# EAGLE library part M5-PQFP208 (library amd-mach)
AMD MACH SERIES
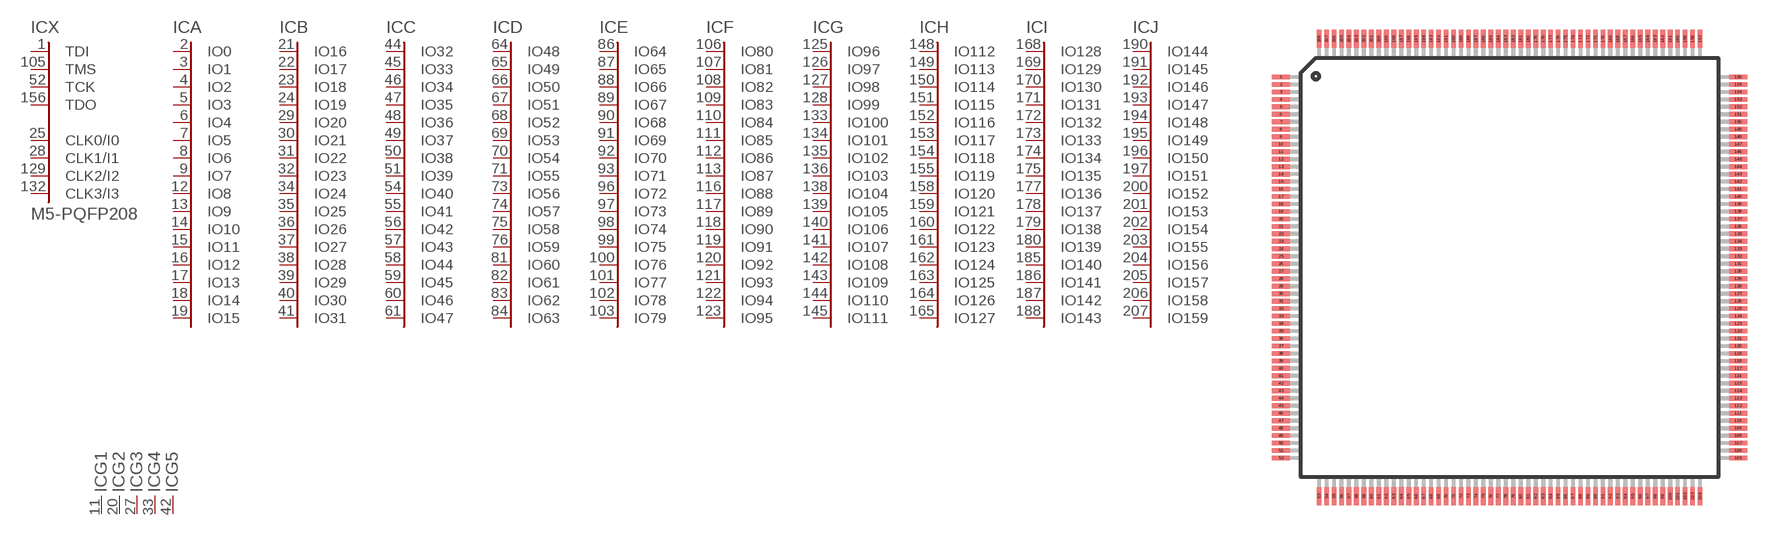
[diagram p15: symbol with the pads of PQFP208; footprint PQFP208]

Designator prefix IC; gates X=M5-CTRL A=IO15 B=IO31 C=IO47 D=IO63 E=IO79 F=IO95 G=IO111 H=IO127 I=IO143 J=IO159 G1=GND G2=GND G3=GND G4=GND G5=GND G6=GND G7=GND G8=GND G9=GND G10=GND G11=GND G12=GND G13=GND G14=GND G15=GND G16=GND G17=GND G18=GND G19=GND G20=GND G21=GND G22=GND G23=GND G24=GND G25=GND G26=GND V1=VCC V2=VCC V3=VCC V4=VCC V5=VCC V6=VCC V7=VCC V8=VCC V9=VCC V10=VCC V11=VCC V12=VCC V13=VCC V14=VCC

## M5-PQFP208 (OC_FARNELL: unknown; OC_NEWARK: unknown)  [PQFP208]
1  X:TDI  in
2  A:IO0
3  A:IO1
4  A:IO2
5  A:IO3
6  A:IO4
7  A:IO5
8  A:IO6
9  A:IO7
10  V1:VCC  pwr
11  G1:GND  pwr
12  A:IO8
13  A:IO9
14  A:IO10
15  A:IO11
16  A:IO12
17  A:IO13
18  A:IO14
19  A:IO15
20  G2:GND  pwr
21  B:IO16
22  B:IO17
23  B:IO18
24  B:IO19
25  X:CLK0/I0  in
26  V2:VCC  pwr
27  G3:GND  pwr
28  X:CLK1/I1  in
29  B:IO20
30  B:IO21
31  B:IO22
32  B:IO23
33  G4:GND  pwr
34  B:IO24
35  B:IO25
36  B:IO26
37  B:IO27
38  B:IO28
39  B:IO29
40  B:IO30
41  B:IO31
42  G5:GND  pwr
43  V3:VCC  pwr
44  C:IO32
45  C:IO33
46  C:IO34
47  C:IO35
48  C:IO36
49  C:IO37
50  C:IO38
51  C:IO39
52  X:TCK  in
53  G6:GND  pwr
54  C:IO40
55  C:IO41
56  C:IO42
57  C:IO43
58  C:IO44
59  C:IO45
60  C:IO46
61  C:IO47
62  G7:GND  pwr
63  V4:VCC  pwr
64  D:IO48
65  D:IO49
66  D:IO50
67  D:IO51
68  D:IO52
69  D:IO53
70  D:IO54
71  D:IO55
72  G8:GND  pwr
73  D:IO56
74  D:IO57
75  D:IO58
76  D:IO59
77  V5:VCC  pwr
78  G9:GND  pwr
79  G10:GND  pwr
80  V6:VCC  pwr
81  D:IO60
82  D:IO61
83  D:IO62
84  D:IO63
85  G11:GND  pwr
86  E:IO64
87  E:IO65
88  E:IO66
89  E:IO67
90  E:IO68
91  E:IO69
92  E:IO70
93  E:IO71
94  V7:VCC  pwr
95  G12:GND  pwr
96  E:IO72
97  E:IO73
98  E:IO74
99  E:IO75
100  E:IO76
101  E:IO77
102  E:IO78
103  E:IO79
104  G13:GND  pwr
105  X:TMS  in
106  F:IO80
107  F:IO81
108  F:IO82
109  F:IO83
110  F:IO84
111  F:IO85
112  F:IO86
113  F:IO87
114  V8:VCC  pwr
115  G14:GND  pwr
116  F:IO88
117  F:IO89
118  F:IO90
119  F:IO91
120  F:IO92
121  F:IO93
122  F:IO94
123  F:IO95
124  G15:GND  pwr
125  G:IO96
126  G:IO97
127  G:IO98
128  G:IO99
129  X:CLK2/I2  in
130  V9:VCC  pwr
131  G16:GND  pwr
132  X:CLK3/I3  in
133  G:IO100
134  G:IO101
135  G:IO102
136  G:IO103
137  G17:GND  pwr
138  G:IO104
139  G:IO105
140  G:IO106
141  G:IO107
142  G:IO108
143  G:IO109
144  G:IO110
145  G:IO111
146  G18:GND  pwr
147  V10:VCC  pwr
148  H:IO112
149  H:IO113
150  H:IO114
151  H:IO115
152  H:IO116
153  H:IO117
154  H:IO118
155  H:IO119
156  X:TDO  in
157  G19:GND  pwr
158  H:IO120
159  H:IO121
160  H:IO122
161  H:IO123
162  H:IO124
163  H:IO125
164  H:IO126
165  H:IO127
166  G20:GND  pwr
167  V11:VCC  pwr
168  I:IO128
169  I:IO129
170  I:IO130
171  I:IO131
172  I:IO132
173  I:IO133
174  I:IO134
175  I:IO135
176  G21:GND  pwr
177  I:IO136
178  I:IO137
179  I:IO138
180  I:IO139
181  V12:VCC  pwr
182  G22:GND  pwr
183  G23:GND  pwr
184  V13:VCC  pwr
185  I:IO140
186  I:IO141
187  I:IO142
188  I:IO143
189  G24:GND  pwr
190  J:IO144
191  J:IO145
192  J:IO146
193  J:IO147
194  J:IO148
195  J:IO149
196  J:IO150
197  J:IO151
198  V14:VCC  pwr
199  G25:GND  pwr
200  J:IO152
201  J:IO153
202  J:IO154
203  J:IO155
204  J:IO156
205  J:IO157
206  J:IO158
207  J:IO159
208  G26:GND  pwr

## Footprint PQFP208 (pad centres in mm)
PLASTIC QUAD FLAT PACK
smd 1.2 x 0.32: 1 -15.3,12.75; 2 -15.3,12.25; 3 -15.3,11.75; 4 -15.3,11.25; 5 -15.3,10.75; 6 -15.3,10.25; 7 -15.3,9.75; 8 -15.3,9.25; 9 -15.3,8.75; 10 -15.3,8.25; 11 -15.3,7.75; 12 -15.3,7.25; 13 -15.3,6.75; 14 -15.3,6.25; 15 -15.3,5.75; 16 -15.3,5.25; 17 -15.3,4.75; 18 -15.3,4.25; 19 -15.3,3.75; 20 -15.3,3.25; 21 -15.3,2.75; 22 -15.3,2.25; 23 -15.3,1.75; 24 -15.3,1.25; 25 -15.3,0.75; 26 -15.3,0.25; 27 -15.3,-0.25; 28 -15.3,-0.75; 29 -15.3,-1.25; 30 -15.3,-1.75; 31 -15.3,-2.25; 32 -15.3,-2.75; 33 -15.3,-3.25; 34 -15.3,-3.75; 35 -15.3,-4.25; 36 -15.3,-4.75; 37 -15.3,-5.25; 38 -15.3,-5.75; 39 -15.3,-6.25; 40 -15.3,-6.75; 41 -15.3,-7.25; 42 -15.3,-7.75; 43 -15.3,-8.25; 44 -15.3,-8.75; 45 -15.3,-9.25; 46 -15.3,-9.75; 47 -15.3,-10.25; 48 -15.3,-10.75; 49 -15.3,-11.25; 50 -15.3,-11.75; 51 -15.3,-12.25; 52 -15.3,-12.75; 105 15.3,-12.75; 106 15.3,-12.25; 107 15.3,-11.75; 108 15.3,-11.25; 109 15.3,-10.75; 110 15.3,-10.25; 111 15.3,-9.75; 112 15.3,-9.25; 113 15.3,-8.75; 114 15.3,-8.25; 115 15.3,-7.75; 116 15.3,-7.25; 117 15.3,-6.75; 118 15.3,-6.25; 119 15.3,-5.75; 120 15.3,-5.25; 121 15.3,-4.75; 122 15.3,-4.25; 123 15.3,-3.75; 124 15.3,-3.25; 125 15.3,-2.75; 126 15.3,-2.25; 127 15.3,-1.75; 128 15.3,-1.25; 129 15.3,-0.75; 130 15.3,-0.25; 131 15.3,0.25; 132 15.3,0.75; 133 15.3,1.25; 134 15.3,1.75; 135 15.3,2.25; 136 15.3,2.75; 137 15.3,3.25; 138 15.3,3.75; 139 15.3,4.25; 140 15.3,4.75; 141 15.3,5.25; 142 15.3,5.75; 143 15.3,6.25; 144 15.3,6.75; 145 15.3,7.25; 146 15.3,7.75; 147 15.3,8.25; 148 15.3,8.75; 149 15.3,9.25; 150 15.3,9.75; 151 15.3,10.25; 152 15.3,10.75; 153 15.3,11.25; 154 15.3,11.75; 155 15.3,12.25; 156 15.3,12.75
smd 0.32 x 1.2: 53 -12.75,-15.3; 54 -12.25,-15.3; 55 -11.75,-15.3; 56 -11.25,-15.3; 57 -10.75,-15.3; 58 -10.25,-15.3; 59 -9.75,-15.3; 60 -9.25,-15.3; 61 -8.75,-15.3; 62 -8.25,-15.3; 63 -7.75,-15.3; 64 -7.25,-15.3; 65 -6.75,-15.3; 66 -6.25,-15.3; 67 -5.75,-15.3; 68 -5.25,-15.3; 69 -4.75,-15.3; 70 -4.25,-15.3; 71 -3.75,-15.3; 72 -3.25,-15.3; 73 -2.75,-15.3; 74 -2.25,-15.3; 75 -1.75,-15.3; 76 -1.25,-15.3; 77 -0.75,-15.3; 78 -0.25,-15.3; 79 0.25,-15.3; 80 0.75,-15.3; 81 1.25,-15.3; 82 1.75,-15.3; 83 2.25,-15.3; 84 2.75,-15.3; 85 3.25,-15.3; 86 3.75,-15.3; 87 4.25,-15.3; 88 4.75,-15.3; 89 5.25,-15.3; 90 5.75,-15.3; 91 6.25,-15.3; 92 6.75,-15.3; 93 7.25,-15.3; 94 7.75,-15.3; 95 8.25,-15.3; 96 8.75,-15.3; 97 9.25,-15.3; 98 9.75,-15.3; 99 10.25,-15.3; 100 10.75,-15.3; 101 11.25,-15.3; 102 11.75,-15.3; 103 12.25,-15.3; 104 12.75,-15.3; 157 12.75,15.3; 158 12.25,15.3; 159 11.75,15.3; 160 11.25,15.3; 161 10.75,15.3; 162 10.25,15.3; 163 9.75,15.3; 164 9.25,15.3; 165 8.75,15.3; 166 8.25,15.3; 167 7.75,15.3; 168 7.25,15.3; 169 6.75,15.3; 170 6.25,15.3; 171 5.75,15.3; 172 5.25,15.3; 173 4.75,15.3; 174 4.25,15.3; 175 3.75,15.3; 176 3.25,15.3; 177 2.75,15.3; 178 2.25,15.3; 179 1.75,15.3; 180 1.25,15.3; 181 0.75,15.3; 182 0.25,15.3; 183 -0.25,15.3; 184 -0.75,15.3; 185 -1.25,15.3; 186 -1.75,15.3; 187 -2.25,15.3; 188 -2.75,15.3; 189 -3.25,15.3; 190 -3.75,15.3; 191 -4.25,15.3; 192 -4.75,15.3; 193 -5.25,15.3; 194 -5.75,15.3; 195 -6.25,15.3; 196 -6.75,15.3; 197 -7.25,15.3; 198 -7.75,15.3; 199 -8.25,15.3; 200 -8.75,15.3; 201 -9.25,15.3; 202 -9.75,15.3; 203 -10.25,15.3; 204 -10.75,15.3; 205 -11.25,15.3; 206 -11.75,15.3; 207 -12.25,15.3; 208 -12.75,15.3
